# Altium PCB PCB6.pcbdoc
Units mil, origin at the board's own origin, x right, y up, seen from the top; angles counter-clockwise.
Board outline 1129.92 x 2677.83 mil, 2 copper layers (Top Layer, Bottom Layer); 45 components, 25 nets, 185 pads, 32 vias.
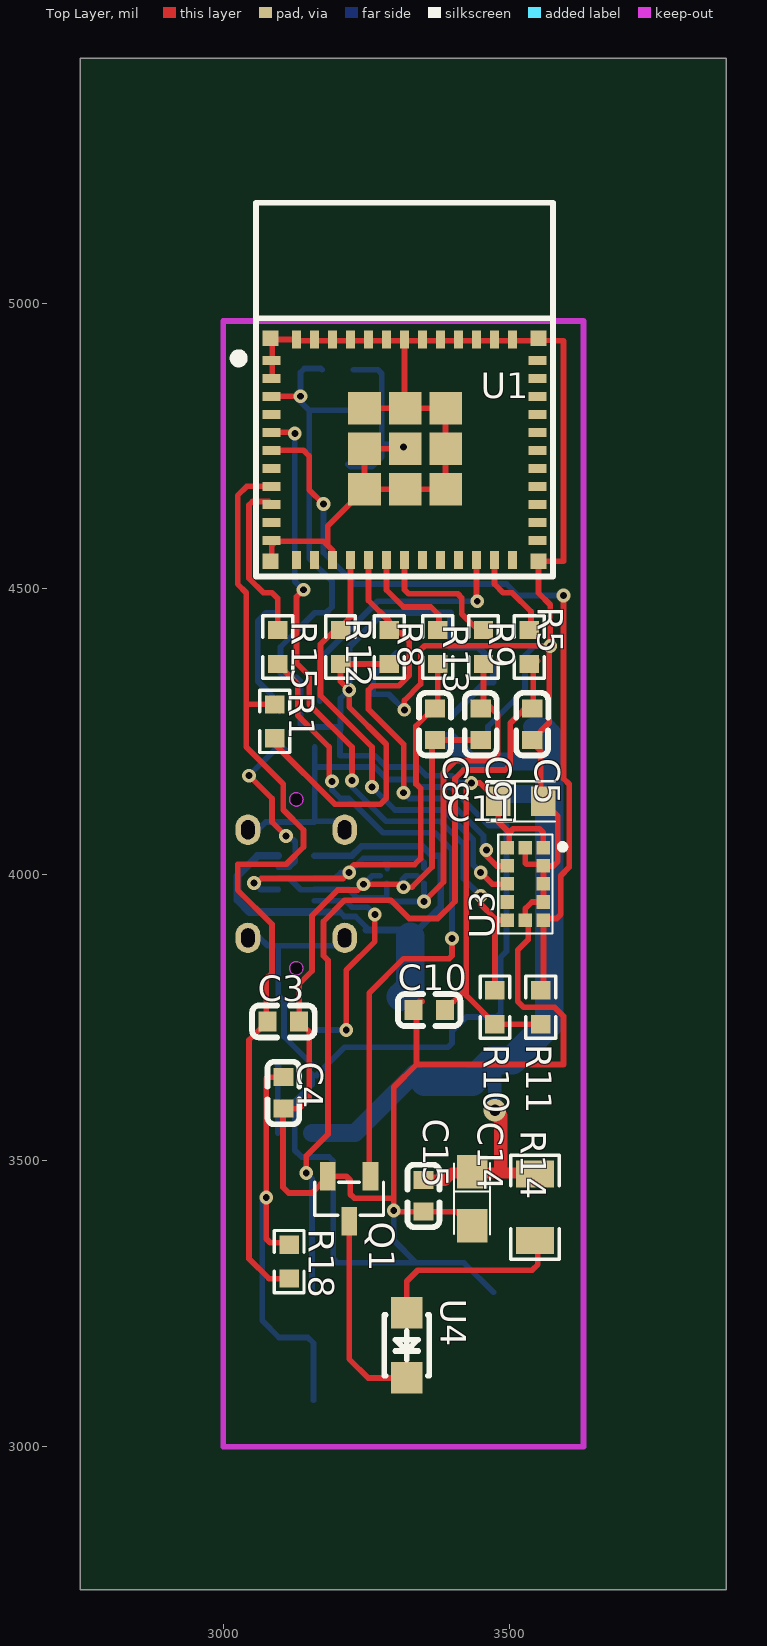
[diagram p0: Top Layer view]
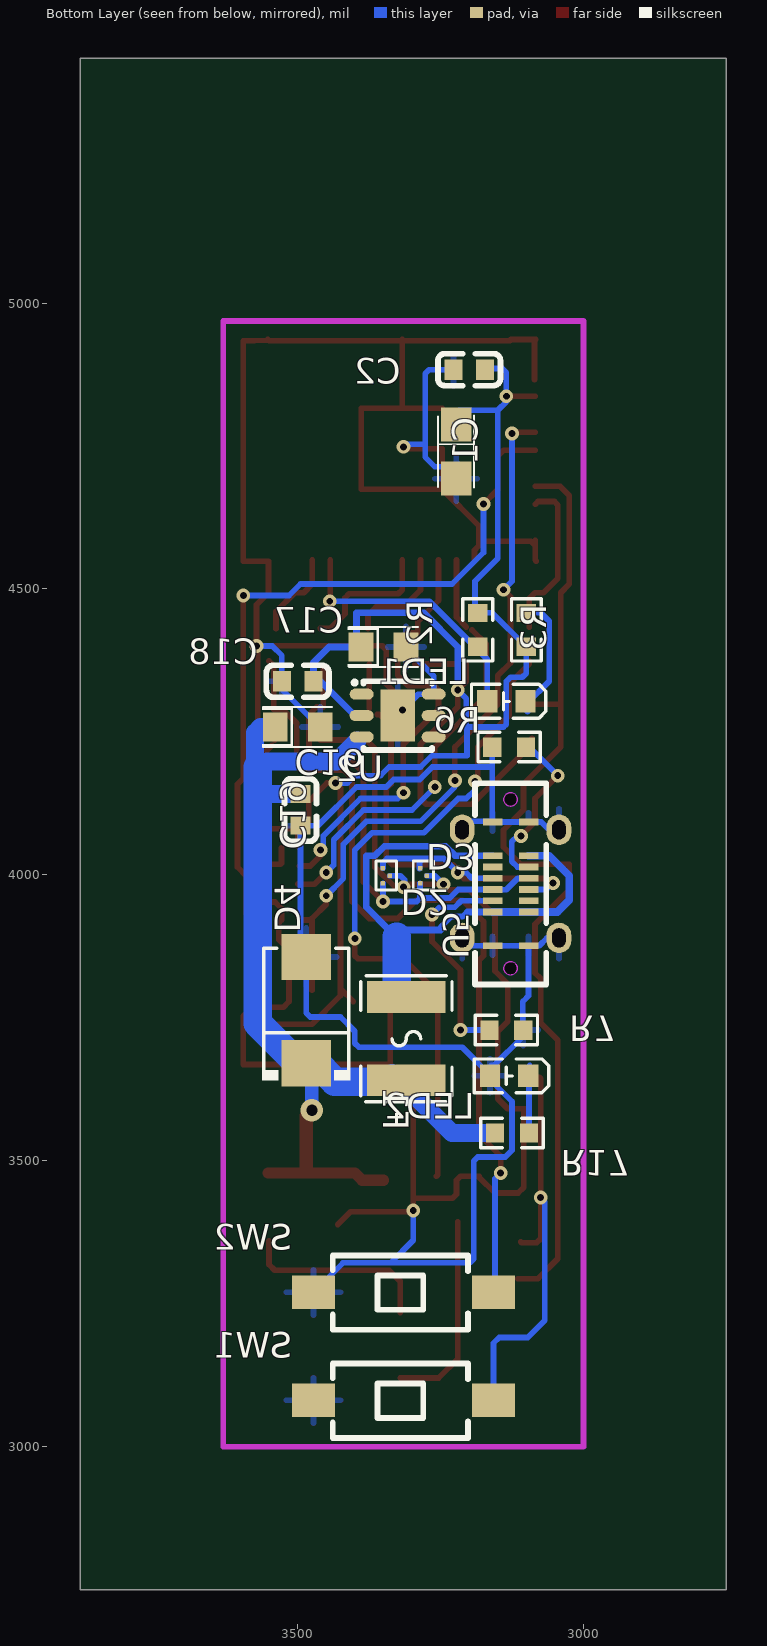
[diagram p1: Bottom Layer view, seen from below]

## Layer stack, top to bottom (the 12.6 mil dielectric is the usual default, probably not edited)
Top Layer: signal copper (thickness not stored)
Dielectric: dielectric 12.6, FR-4, Dk 4.8
Bottom Layer: signal copper (thickness not stored)

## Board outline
3879.92,2750 2750,2750 2750,5427.83 3879.92,5427.83

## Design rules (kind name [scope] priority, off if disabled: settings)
BoardOutlineClearance copperThickness1oz [All] p0: genericclearance=10 ignorepadtopadclearanceinfootprint=FALSE except(0: Arc-SplitContinuation Track-SplitContinuation SMDPad-SplitContinuation THPad-SplitContinuation Via-SplitContinuation Fill-SplitContinuation Poly-SplitContinuation Region-SplitContinuation Text-SplitContinuation; 6: Track-CutoutEdge SMDPad-CutoutEdge THPad-CutoutEdge Via-CutoutEdge Region-CutoutEdge; 11.8: Track-OutlineEdge SMDPad-OutlineEdge THPad-OutlineEdge Via-OutlineEdge Fill-OutlineEdge Region-OutlineEdge Poly-OutlineEdge Text-OutlineEdge Fill-CutoutEdge)
BoardOutlineClearance copperThickness2oz [All] p0: genericclearance=10 ignorepadtopadclearanceinfootprint=FALSE except(0: Arc-SplitContinuation Track-SplitContinuation SMDPad-SplitContinuation THPad-SplitContinuation Via-SplitContinuation Fill-SplitContinuation Poly-SplitContinuation Region-SplitContinuation Text-SplitContinuation; 6: Track-CutoutEdge SMDPad-CutoutEdge THPad-CutoutEdge Via-CutoutEdge Region-CutoutEdge; 11.8: Track-OutlineEdge SMDPad-OutlineEdge THPad-OutlineEdge Via-OutlineEdge Fill-OutlineEdge Region-OutlineEdge Poly-OutlineEdge Text-OutlineEdge Fill-CutoutEdge)
Clearance copperThickness1oz [(InNet('VDD33') OR InNet('GND') OR InNet('$3N5376') OR InNet('+5V_USB') OR InNet('GPIO12_USB_DN') OR InNet('GPIO13_USB_DP') OR InNet('$3N4848') OR InNet('$3N6215') OR InNet('$3N11377') OR InNet('$3N11381') OR InNet('$3N7934') OR InNet('$3N7054') OR InNet('$3N7060') OR InNet('GPIO2') OR InNet('GPIO3') OR InNet('I2C_SDA') OR InNet('I2C_SCL') OR InNet('$3N11357') OR InNet('GPIO4') OR InNet('$3N14553') OR InNet('$3N17638') OR InNet('$3N17354') OR InNet('$3N18951') OR InNet('$3N23650') OR InNet('$3N23645'))] p1: gap=7 ignorepadtopadclearanceinfootprint=FALSE except(4: Track-Track; 6: Track-SMDPad SMDPad-SMDPad Track-THPad SMDPad-THPad THPad-THPad Track-Via SMDPad-Via THPad-Via Via-Via SMDPad-Fill THPad-Fill Via-Fill Fill-Fill Track-Region SMDPad-Region THPad-Region Via-Region Region-Region Track-Poly SMDPad-Poly THPad-Poly Via-Poly Fill-Poly Region-Poly Poly-Poly Track-Text SMDPad-Text THPad-Text Via-Text Fill-Text Region-Text Poly-Text Text-Text; 6.9: Track-Hole SMDPad-Hole THPad-Hole Via-Hole Fill-Hole Region-Hole Poly-Hole Text-Hole Sheet-Hole; 11.8: Track-Fill Fill-Region Track-Sheet SMDPad-Sheet THPad-Sheet Via-Sheet Fill-Sheet Region-Sheet Poly-Sheet Text-Sheet)
Clearance copperThickness2oz [All] p1: gap=7 ignorepadtopadclearanceinfootprint=FALSE except(6: Track-SMDPad SMDPad-SMDPad Track-THPad SMDPad-THPad THPad-THPad Track-Via SMDPad-Via THPad-Via Via-Via SMDPad-Fill THPad-Fill Via-Fill Fill-Fill Track-Region SMDPad-Region THPad-Region Via-Region Region-Region Track-Poly SMDPad-Poly THPad-Poly Via-Poly Fill-Poly Region-Poly Poly-Poly Track-Text SMDPad-Text THPad-Text Via-Text Fill-Text Region-Text Poly-Text Text-Text; 6.9: Track-Hole SMDPad-Hole THPad-Hole Via-Hole Fill-Hole Region-Hole Poly-Hole Text-Hole Sheet-Hole; 8: Track-Track; 11.8: Track-Fill Fill-Region Track-Sheet SMDPad-Sheet THPad-Sheet Via-Sheet Fill-Sheet Region-Sheet Poly-Sheet Text-Sheet)
DiffPairsRouting differentialPair [All] p1: maxuncoupledlength=10 minlimit=6 maxlimit=6 mostfreqgap=6 toplayer_minwidth=5 toplayer_prefwidth=10 toplayer_maxwidth=100 bottomlayer_minwidth=5 bottomlayer_prefwidth=10 bottomlayer_maxwidth=100
PasteMaskExpansion pasteMaskExpansion [All] p1: expansion=0
PlaneConnect innerPlane [All] p1: planeconnectstyle=Relief reliefexpansion=20 reliefentries=4 reliefconductorwidth=10 reliefairgap=10
PolygonConnect copperRegion [All] p1: connectstyle=Relief reliefentries=4 reliefconductorwidth=10 polygonreliefangle="90 Angle" airgapwidth=10
RoutingVias viaSize [All] p1: viastyle="Through Hole" holewidth=12.0078 minholewidth=11.811 maxholewidth=248.0314 width=24.0158 minwidth=19.685 maxwidth=393.7008
SolderMaskExpansion solderMaskExpansion [All] p1: useseparateexpansions=TRUE expansion=2 expansionbottom=2
Width copperThickness1oz [All] p1: maxlimit=100 minlimit=5 preferedwidth=10
Width copperThickness2oz [All] p1: maxlimit=100 minlimit=8 preferedwidth=10

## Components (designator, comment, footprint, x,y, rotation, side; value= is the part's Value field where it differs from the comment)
C1 "" CASE-A_3216 3222.86,4740.18 r270 bottom
C2 "" C0603 3200,4883.5 r180 bottom
C3 "" C0603 3105,3743.5 r0 top
C4 "" C0603 3105,3618.5 r270 top
C5 "" C0603 3540,4263.5 r270 top
C8 "" C0603 3370,4263.5 r270 top
C9 "" C0603 3450,4263.5 r270 top
C10 "" C0603 3360,3763.5 r180 top
C11 "" CAP-SMD_L2.0-W1.3-FD 3520,4128.5 r0 top
C14 "" CASE-A_3216 3435,3433.5 r270 top
C15 "" C0603 3350,3438.5 r90 top
C16 "" C0603 3500,4338.5 r0 bottom
C17 "" CAP-SMD_L2.0-W1.3-FD 3350,4398.5 r180 bottom
C18 "" CAP-SMD_L2.0-W1.3-FD 3500,4258.5 r180 bottom
C19 "" C0603 3495,4113.5 r270 bottom
D2 "" X2SON-3_L1.0-W0.6-L 3280,3998.5 r0 bottom
D3 "" X2SON-3_L1.0-W0.6-L 3345,3998.5 r0 bottom
D4 "" SMB_L4.6-W3.6-LS5.3-RD 3485,3763.5 r90 bottom
F1 "" F1812 3310,3713.5 r90 bottom
LED1 "" LED0603-FD 3135,4303.5 r180 bottom
LED2 "" LED0603-FD 3130,3648.5 r180 bottom
Q1 "" SOT-23-3_L2.9-W1.3-P1.90-LS2.4-BR 3220,3433.5 r90 top
R1 "" R0603 3090,4268.5 r270 top
R2 "" R0603 3185,4428.5 r90 bottom
R3 "" R0603 3100,4428.5 r270 bottom
R5 "" R0603 3535,4398.5 r90 top
R6 "" R0603 3130,4223.5 r180 bottom
R7 "" R0603 3135,3728.5 r0 bottom
R8 "" R0603 3375,4398.5 r90 top
R9 "" R0603 3455,4398.5 r90 top
R10 "" R0603 3475,3768.5 r270 top
R11 "" R0603 3555,3768.5 r270 top
R12 "" R0603 3205,4398.5 r270 top
R13 "" R0603 3290,4398.5 r270 top
R14 "" R1206 3545,3418.5 r270 top
R15 "" R0603 3095,4398.5 r270 top
R17 "" R0603 3125,3548.5 r180 bottom
R18 "" R0603 3115,3323.5 r270 top
SW1 "" SW-SMD_L6.0-W3.3-LS8.0 3314.96,3080.96 r180 bottom locked
SW2 "" SW-SMD_L6.0-W3.3-LS8.0 3314.96,3269.88 r180 bottom locked
U1 "" WIFIM-SMD_61P-L16.6-W13.2-P0.80-ESP32-C6-MINI-1-N4 3316.83,4743.38 r0 top locked
U2 "" DFN-6_L3.0-W3.0-P0.95-BL-EP-1 3325,4278.5 r270 bottom
U3 "" OPTO-SMD_12P_VL53L3CXV0DH 3528.2,3984.01 r90 top locked
U4 "" LED-SMD_L3.0-W2.0-R-RD 3320.66,3177.16 r90 top locked
U5 "" TYPE-C-SMD_USB4120-03-C 3127.63,3984.25 r90 bottom locked

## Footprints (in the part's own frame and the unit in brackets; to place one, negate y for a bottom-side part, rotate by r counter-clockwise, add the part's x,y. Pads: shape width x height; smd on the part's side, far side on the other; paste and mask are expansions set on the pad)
C0603 [mm]
  rect 0.8x0.9 smd: 1(-0.7,0) 2(0.7,0)
  silkscreen extent -1.39,-0.71 1.39,0.71
CAP-SMD_L2.0-W1.3-FD [mm]
  rect 1.1x1.3 smd: 1(-1,0) 2(1,0)
  silkscreen extent -1.57,-0.89 1.52,0.89
CASE-A_3216 [mil]
  rect 59.05x53.5 smd: 1(-47.24,0) 2(47.24,0)
  silkscreen extent -63,-32 63,32
DFN-6_L3.0-W3.0-P0.95-BL-EP-1 [mm]
  oval 0.49x1.07 smd: 1(-0.95,-1.6) 2(0,-1.6) 3(0.95,-1.6) 4(0.95,1.6) 5(0,1.6) 6(-0.95,1.6)
  rect 2.3x1.55 smd: 7(0,0)
  silkscreen extent -1.56,-2 1.52,1.52
F1812 [mil]
  rect 55.38x137.76 smd: 1(-72.97,0) 2(72.97,0)
  silkscreen extent -110,-80 110,80
LED0603-FD [mm]
  rect 0.9x1 smd: 1(-0.85,0) 2(0.85,0)
  silkscreen extent -1.55,-0.75 1.75,0.75
LED-SMD_L3.0-W2.0-R-RD [mm]
  rect 1.4x1.4 smd: 1(1.45,0) 2(-1.45,0)
  silkscreen extent -1.35,-1 1.35,1
OPTO-SMD_12P_VL53L3CXV0DH [mm]
  rect 0.6x0.6 smd: 1(1.6,-0.8) 2(0.8,-0.8) 3(0,-0.8) 4(-0.8,-0.8) 5(-1.6,-0.8) 6(-1.6,0) 7(-1.6,0.8) 8(-0.8,0.8) 9(0,0.8) 10(0.8,0.8) 11(1.6,0.8) 12(1.6,0)
  silkscreen extent -2.2,-1.78 2.2,1.2
R0603 [mil]
  rect 31.75x34.02 smd: 1(-29.66,0) 2(29.66,0)
  silkscreen extent -55,-26 55,26
R1206 [mil]
  rect 47.54x66.97 smd: 1(-58.22,0) 2(58.22,0)
  silkscreen extent -91,-42 91,42
SMB_L4.6-W3.6-LS5.3-RD [mil]
  rect 80.61x86.31 smd: 1(-92.94,0) 2(92.94,0)
  silkscreen extent -123,-77 108,77
SOT-23-3_L2.9-W1.3-P1.90-LS2.4-BR [mm]
  rect 1.25x0.7 smd: 1(1,-0.95) 2(1,0.95) 3(-1,0)
  silkscreen extent -0.73,-1.53 0.73,1.53
SW-SMD_L6.0-W3.3-LS8.0 [mm]
  rect 1.9x1.5 smd: 1(-4,0) 2(4,0)
  silkscreen extent -3.14,-1.67 2.86,1.63
TYPE-C-SMD_USB4120-03-C [mm]
  oval 1.35x1.1 hole 0.6 slot 0.85 at 0 deg: 0(-2.4,-2.15) 0(-2.4,2.15) 0(2.4,-2.15) 0(2.4,2.15)
  rect 0.3x0.87 smd: A1(-2.75,0.8) A4(-1.25,0.8) A5(-0.75,0.8) A6(-0.25,0.8) A7(0.25,0.8) A8(0.75,0.8) A9(1.25,0.8) A12(2.75,0.8) B1(2.75,-0.8) B4(1.25,-0.8) B5(0.75,-0.8) B6(0.25,-0.8) B7(-0.25,-0.8) B8(-0.75,-0.8) B9(-1.25,-0.8) B12(-2.75,-0.8)
  Board Outline Layer circle w0.005: c-3.75,0 r0.3
  Board Outline Layer circle w0.005: c3.75,0 r0.3
  Board Outline Layer region: -3.75,0.3 -3.88,0.27 -3.985,0.187 -4.043,0.067 -4.043,-0.067 -3.985,-0.187 -3.88,-0.27 -3.75,-0.3 -3.75,-0.3 -3.62,-0.27 -3.516,-0.187 -3.458,-0.067 -3.458,0.067 -3.516,0.187 -3.62,0.27 -3.75,0.3
  Board Outline Layer region: 3.75,0.3 3.62,0.27 3.516,0.187 3.458,0.067 3.458,-0.067 3.516,-0.187 3.62,-0.27 3.75,-0.3 3.75,-0.3 3.88,-0.27 3.985,-0.187 4.043,-0.067 4.043,0.067 3.985,0.187 3.88,0.27 3.75,0.3
  Multi-Layer board cut-out: -3.75,0.3 -3.88,0.27 -3.985,0.187 -4.043,0.067 -4.043,-0.067 -3.985,-0.187 -3.88,-0.27 -3.75,-0.3 -3.75,-0.3 -3.62,-0.27 -3.516,-0.187 -3.458,-0.067 -3.458,0.067 -3.516,0.187 -3.62,0.27 -3.75,0.3
  Multi-Layer board cut-out: 3.75,0.3 3.62,0.27 3.516,0.187 3.458,0.067 3.458,-0.067 3.516,-0.187 3.62,-0.27 3.75,-0.3 3.75,-0.3 3.88,-0.27 3.985,-0.187 4.043,-0.067 4.043,0.067 3.985,0.187 3.88,0.27 3.75,0.3
  silkscreen extent -4.47,-1.58 4.47,1.58
WIFIM-SMD_61P-L16.6-W13.2-P0.80-ESP32-C6-MINI-1-N4 [mm]
  rect 0.8x0.4 smd: 1(-5.9,3.975) 2(-5.9,3.175) 3(-5.9,2.375) 4(-5.9,1.575) 5(-5.9,0.775) 6(-5.9,-0.025) 7(-5.9,-0.825) 8(-5.9,-1.625) 9(-5.9,-2.425) 10(-5.9,-3.225) 11(-5.9,-4.025) 25(5.9,-4.025) 26(5.9,-3.225) 27(5.9,-2.425) 28(5.9,-1.625) 29(5.9,-0.825) 30(5.9,-0.025) 31(5.9,0.775) 32(5.9,1.575) 33(5.9,2.375) 34(5.9,3.175) 35(5.9,3.975)
  rect 0.4x0.8 smd: 12(-4.8,-4.9) 13(-4,-4.9) 14(-3.2,-4.9) 15(-2.4,-4.9) 16(-1.6,-4.9) 17(-0.8,-4.9) 18(0,-4.9) 19(0.8,-4.9) 20(1.6,-4.9) 21(2.4,-4.9) 22(3.2,-4.9) 23(4,-4.9) 24(4.8,-4.9) 36(4.8,4.9) 37(4,4.9) 38(3.2,4.9) 39(2.4,4.9) 40(1.6,4.9) 41(0.8,4.9) 42(0,4.9) 43(-0.8,4.9) 44(-1.6,4.9) 45(-2.4,4.9) 46(-3.2,4.9) 47(-4,4.9) 48(-4.8,4.9)
  rect 1.45x1.45 smd: 49(-1.775,-1.75) 49(-1.775,0.05) 49(-1.775,1.85) 49(0.025,-1.75) 49(0.025,0.05) 49(0.025,1.85) 49(1.825,-1.75) 49(1.825,0.05) 49(1.825,1.85)
  rect 0.7x0.7 smd: 50(5.95,4.95) 51(5.95,-4.95) 52(-5.95,-4.95) 53(-5.95,4.95)
  silkscreen extent -7.57,-5.62 6.6,10.98
X2SON-3_L1.0-W0.6-L [mm]
  rect 0.2x0.2 smd: 1(-0.15,0) 2(0.15,-0.34) 3(0.15,0.34)
  silkscreen extent -0.45,-0.66 0.45,0.64

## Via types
v1: diameter 24.02, hole 12.01, Top Layer to Bottom Layer, 31 vias
v2: diameter 39.37, hole 19.68, Top Layer to Bottom Layer, 1 vias

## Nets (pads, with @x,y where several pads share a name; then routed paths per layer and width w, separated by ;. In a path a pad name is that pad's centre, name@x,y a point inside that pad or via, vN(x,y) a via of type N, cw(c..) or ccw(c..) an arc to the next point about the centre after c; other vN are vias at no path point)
$3N4848: LED1.1 R2.1 U1.22 | length 463.5
  Top Layer w10: U1.22 3442.81,4479.65 v1(3443.96,4478.5)
  Bottom Layer w10: LED1.1 3168.47,4376.97 3270,4478.5 v1(3443.96,4478.5)
$3N5376: C5.1 R5.1 SW2.2 | length 1476.6
  Top Layer w10: v1(3145,3478.5) 3145,3508.5 3182.93,3546.43 3182.93,3850.57 3175,3858.5 3175,3918.5 3211.95,3955.45 3293.01,3955.5 3325,3923.5 3375,3923.5 3405,3953.5 3405,4168.5 3420,4183.5 3492.57,4183.5 3501.72,4192.65 3501.72,4265.22 3525,4288.5 3541.91,4288.5 3541.91,4365.76 R5.1@3550,4373.84
  Bottom Layer w10: v1(3145,3478.5) 3155,3468.5 3155,3272.36 SW2.2
$3N6215: LED1.2 R3.1 | length 209.7
  Bottom Layer w10: R3.1@3089.66,4458.5 3075,4458.5 3060,4443.5 3060,4338.5 3098.1,4300.4 LED1.2@3098.1,4285.43
$3N7054: R8.2 U1.17 | length 186.3
  Top Layer w10: U1.17 3285.33,4498.17 3315,4468.5 3362.93,4468.5 3377.07,4454.36 R8.2@3377.07,4430.23
$3N7060: R9.2 U1.18 | length 240.3
  Top Layer w10: U1.18 3316.82,4498.5 3323.89,4491.43 3410,4491.43 3417.07,4484.36 3417.07,4456.43 3442.07,4431.43 3459.9,4431.43 R9.2@3460.67,4430.67
$3N7934: R5.2 U1.23 | length 155.8
  Top Layer w10: U1.23 3474.31,4508.5 3489.31,4493.5 3505,4493.5 3537.93,4460.57 R5.2@3537.93,4430.23
$3N11357: R14.2 U4.1 | length 338.2
  Top Layer w10: U4.1 3320.66,3289.17 3340,3308.5 3540,3308.5 3550,3318.5 R14.2@3550,3360.28
$3N11377: Q1.1 R15.2 | length 1196.7
  Top Layer w10: R15.2@3095,4373.84 R15.2 3130,4333.84 3130,4278.5 3185,4223.5 3185,4168.5 v1(3190,4163.5) ; Q1.1 3255,3475.27 3255,3793.5 3315,3853.5 3395,3853.5 3400,3858.5 v1(3400,3888.5)
  Bottom Layer w10: v1(3190,4163.5) 3190,4148.5 3205,4133.5 3219.14,4133.5 3279.14,4073.5 3370,4073.5 3400,4043.5 v1(3400,3888.5)
$3N11381: Q1.3 U4.2 | length 354.5
  Top Layer w10: Q1.3@3220,3393.5 3220,3153.5 3253.44,3120.07 U4.2
$3N14553: LED2.2 R17.2 | length 135.9
  Bottom Layer w10: LED2.2@3094.2,3666.56 LED2.2@3095.34,3665.42 ; R17.2 LED2.2@3095.34,3665.42 ; LED2.2 3096.53,3664.23 LED2.2@3095.34,3665.42
$3N17354: R7.2 U5.A5 | length 389
  Top Layer w10: v1(3215,3728.5) 3215,3833.5 3265,3883.5 v1(3265,3930.57)
  Bottom Layer w10: U5.A5 3213.78,3954.72 3225,3943.5 3252.07,3943.5 v1(3265,3930.57) ; R7.2 v1(3215,3728.5)
$3N17638: R6.2 U5.B5 | length 308.1
  Top Layer w10: v1(3045,4173.5) 3085,4133.5 3085,4092.42 v1(3109.55,4067.87)
  Bottom Layer w10: v1(3045,4173.5) 3095,4223.5 3103.53,4223.5 R6.2@3109.44,4217.6 ; U5.B5 3115.73,4013.78 3125.73,4023.78 3125.73,4057.78 3115.64,4067.87 v1(3109.55,4067.87)
$3N18951: F1.2 U5.A4 U5.A9 U5.B4 U5.B9 | length 961
  Bottom Layer w10: 3203.93,3935.04 3211.65,3927.32 3231.18,3927.32 3249.61,3908.9 3249.61,3903.5
  Bottom Layer w11.81: U5.A4 3203.46,3935.04 ; U5.A9 3224.96,4033.46 3241.55,4050.06 3348.45,4050.06 3365,4033.5 3380,4033.5 3380,3943.5 3340,3903.5 3249.61,3903.5
  Bottom Layer w13.78: U5.B4@3096.05,4033.46 3059.96,4033.46 3025,3998.5 3025,3955.92 3045.87,3935.04 U5.B9 U5.A4
  Bottom Layer w50: F1.2 3326.57,3803.04 3326.57,3891.93
$3N23645: C4.1 R18.1 SW1.2 | length 773.8
  Top Layer w10: C4.1 3077.56,3646.06 3075,3643.5 v1(3075,3435.76) 3075,3363.5 3082.07,3356.43 3108.27,3356.43 R18.1@3110,3358.16
  Bottom Layer w10: v1(3075,3435.76) 3067.93,3428.69 3067.93,3220.57 3097.48,3191.02 3147.48,3191.02 3157.48,3181.02 SW1.2
$3N23650: C3.1 R1.1 R18.2 U1.8 | length 1724.1
  Top Layer w10: U1.8 3040.9,4679.4 3025,4663.5 3025,4508.5 3040,4493.5 3040,4298.5 ; R1.1 3055.34,4298.16 3055,4298.5 3040,4298.5 ; R18.2 3079.66,3293.84 3045,3328.5 3045,3711.06 C3.1 3075,3745.94 3075,3818.5 3085,3828.5 3085,3913.5 3025,3973.5 3025,4018.5 3110,4018.5 3140,4048.5 3140,4078.5 3104.83,4113.68 3104.83,4158.68 3040,4223.5 3040,4298.5
+5V_USB: C14.1 C15.2 C18.1 C19.1 D4.1 F1.1 R14.1 R17.1 U2.3 | length 1636.9
  Top Layer w19.68: C15.2 3387.56,3466.06 3400,3478.5 R14.1@3551.78,3478.5
  Top Layer w23.62: v2(3475,3588.5) 3485,3578.5 3485,3488.5
  Bottom Layer w23.62: v2(3475,3588.5) D4.1@3475,3660.56
  Bottom Layer w31.5: R17.1 3230,3548.5 F1.1@3335,3653.5 ; U2.3@3395.38,4235 3431.87,4198.5 3553.3,4198.5 ; C19.1 3552.56,4141.06 3555,4143.5 ; C18.1 3565,4258.5 3575,4248.5 3575,4200.57
  Bottom Layer w50: F1.1@3352.03,3638.5 3435,3638.5 3472.06,3675.56 3505,3675.56 3570,3740.56 3570,4188.5
GND: C1.2 C2.1 C3.2 C4.2 C5.2 C8.2 C9.2 C10.2 C11.2 C14.2 C15.1 C16.2 C17.2 C18.2 C19.2 D2.1 D3.1 D4.2 LED2.1 Q1.2 R6.1 R7.1 SW1.1 SW2.1 U1.1 U1.2 U1.11 U1.14 U1.36 U1.37 U1.38 U1.39 U1.40 U1.41 U1.42 U1.43 U1.44 U1.45 U1.46 U1.47 U1.48 U1.49 U1.50 U1.51 U1.52 U1.53 U2.6 U2.7 U3.2 U3.3 U3.4 U3.6 U3.12 U5.0 U5.A1 U5.A12 U5.B1 U5.B12 | length 8924.5
  Top Layer w10: U1.52 3084.54,4550.47 3084.54,4576.29 ; U1.11 3084.54,4576.29 ; U1.2@3085.69,4866.26 3085.69,4897.76 3085.69,4934.17 3083.72,4936.14 3127.03,4936.14 3129,4934.17 3160.5,4934.17 3191.99,4934.17 U1.42@3316.83,4934.17 ; C4.2@3100,3590.94 C4.2 ; U1.14 3190.84,4567.66 3182.69,4575.81 ; U1.49@3246.94,4816.22 U1.49@3317.81,4816.22 ; v1(3316.59,4288.5) 3316.59,4305.09 3345,4333.5 3345,4393.5 3352.07,4400.57 3571.6,4400.57 v1(3571.83,4400.34) ; U1.42 U1.42@3316.83,4934.17 ; U1.49@3317.81,4745.35 3246.94,4745.35 U1.49@3246.94,4674.49 ; C10.2@3347.44,3778.5 3342.44,3778.5 3337.93,3773.99 3337.93,3668.5 ; C14.2@3430,3388.5 3407.56,3410.94 3365,3410.94 3299.81,3410.94 v1(3297.93,3412.83) 3297.93,3434.32 ; C9.2@3460,4235.94 3380,4235.94 3365,4220.94 3365,4013.5 3329.99,3978.5 v1(3315,3978.5) 3309.99,3983.5 v1(3245,3983.5) 3235,3973.51 3199.99,3973.5 3155,3928.5 3155,3831.75 3132.56,3809.31 C3.2 3150,3726.06 3150,3608.5 3132.44,3590.94 C4.2 ; U3.12 3528.19,4020.31 3530,4018.5 U3.2@3556.69,4018.5 ; C5.2 3570,4265.94 3570,4398.5 v1(3571.83,4400.34) ; C5.2@3545.4,4226.34 3555,4216.74 C11.2@3555,4128.5 ; C11.2 3585,4102.87 3585,4023.5 3576.99,4015.5 U3.2@3560,4015.5 ; U3.2 U3.2@3560,4015.5 ; 3084.54,4576.29 3091.76,4583.5 3175,4583.5 3182.69,4575.81 ; C4.2 3104.37,3590.31 3104.37,3453.5 3114.37,3443.5 3155,3443.5 3182.6,3471.1 Q1.2 3215,3472.87 3222.07,3465.8 3222.07,3441.39 3229.14,3434.32 3297.93,3434.32 ; 3182.69,4575.81 3182.69,4610.25 U1.49@3246.94,4674.49 ; U1.49@3246.94,4674.49 3317.81,4674.49 3388.67,4674.49 3388.67,4745.35 3388.67,4816.22 U1.49@3317.81,4816.22 ; 3297.93,3434.32 3297.93,3628.5 3337.93,3668.5 ; U1.42@3316.83,4934.17 3316.83,4817.2 U1.49@3317.81,4816.22 ; U1.42@3316.83,4934.17 3550.26,4934.17 3552.23,4936.14 3552.23,4934.94 3595,4933.5 3595,4548.5 U1.51 3551.08,4493.1 3571.83,4472.35 v1(3571.83,4400.34) ; 3337.93,3668.5 3595,3668.5 3595,3752.86 3579.36,3768.5 3525,3768.5 3515,3778.5 3515,3868.5 3533.19,3886.7 3533.19,3916.02 U3.6 3528.19,3940.97 3539.74,3952.51 3560,3952.51 U3.2@3560,4015.5
  Bottom Layer w10: U5.0@3042.98,3889.76 3063.74,3889.76 3077.52,3875.98 U5.B12 ; U5.0@3042.98,4078.74 3060.24,4078.74 3074.02,4092.52 U5.B1 U5.A12 U5.A12@3159.66,4093.06 ; LED2.1@3153.47,3652.5 3155,3650.96 3155,3633.5 3125,3603.5 3125,3518.5 3137.01,3506.5 3185,3506.5 3192.07,3499.43 3192.07,3328.5 3199.14,3321.43 3337.36,3321.43 ; R6.1 3159.66,4188.41 ; LED2.1@3161.13,3666.56 3156.94,3666.56 3106.13,3717.37 3106.13,3778.5 3096.13,3788.5 U5.B12 ; LED2.1 3163.47,3649.9 3212.07,3698.5 3392.93,3698.5 3400,3705.57 3400,3726.43 3425,3751.43 3477.93,3751.43 3485,3758.5 D4.2 3495,3866.44 C19.2 3464.8,4085.94 3397.24,4153.5 3345,4153.5 3331.94,4166.56 3286.52,4166.56 3264.67,4188.41 3159.66,4188.41 ; U5.0@3212.27,3889.76 3198.49,3875.98 U5.A1 U5.B12 ; U5.0@3212.27,4078.74 3197.51,4093.5 3160.1,4093.5 U5.A12@3159.66,4093.06 ; C1.2@3217.86,4717.94 3222.3,4713.5 3260,4713.5 3277.07,4730.57 3277.07,4753.11 ; C2.1 3270,4883.5 3277.07,4876.43 3277.07,4753.11 ; v1(3245,3983.5) 3259.99,3998.5 D2.1 ; v1(3297.93,3412.83) 3297.93,3360.86 3337.36,3321.43 ; C17.2@3302.76,4388.5 3262.01,4347.75 U2.6 3289.19,4315.9 v1(3316.59,4288.5) ; v1(3315,3978.5) 3312.93,3980.57 3312.93,3991.43 3320,3998.5 D3.1 ; v1(3315,4748.5) 3310.39,4753.11 3277.07,4753.11 ; C18.2@3462.76,4248.5 3462.76,4259.56 3527.56,4324.36 C16.2 3527.56,4383.5 3544.39,4400.34 v1(3571.83,4400.34) ; SW2.1 3420.89,3321.43 3337.36,3321.43 ; U5.A12@3159.66,4093.06 3159.66,4188.41
GPIO2: R10.1 U1.5 U3.7 | length 1248.3
  Top Layer w10: U1.5 3122.87,4773.89 v1(3125,4771.77) ; v1(3140,4498.5) 3127.93,4486.43 3127.93,4370.57 3150,4348.5 3150,4298.5 3225,4223.5 v1(3225,4165.04) ; v1(3450,3963.5) 3450,3948.5 3475,3923.5 ; R10.1 3475,3923.5 ; U3.7 3477.49,3921.02 3475,3923.5
  Bottom Layer w10: v1(3125,4771.77) 3125,4513.5 v1(3140,4498.5) ; v1(3225,4165.04) 3225,4153.5 3285,4093.5 3380,4093.5 3420,4053.5 3420,3993.5 v1(3450,3963.5)
GPIO3: R11.1 U1.6 U3.5 | length 1427.5
  Top Layer w10: U1.6 3140,4742.4 3150,4732.4 3150,4673.5 v1(3175,4648.5) ; R11.1 3560,3803.16 3560,3920.71 U3.5 3562.18,3923.5 3582.93,3923.5 3590,3930.57 3590,3998.5 3605,4013.5 3605,4158.5 3595,4168.5 v1(3595,4488.5)
  Bottom Layer w10: v1(3175,4648.5) 3175,4563.5 3230,4508.5 3495,4508.5 3515,4488.5 v1(3595,4488.5)
GPIO4: R15.1 U1.9 | length 287.4
  Top Layer w10: U1.9 3079.54,4652.91 3050.98,4652.91 3045,4646.93 3045,4518.5 3070,4493.5 3085,4493.5 3095,4483.5 R15.1@3095,4433.16
GPIO12_USB_DN: C8.1 D2.2 D3.2 R8.1 U5.A7 U5.B7 | length 944.4
  Top Layer w10: v1(3053.58,3985.89) 3058.58,3985.89 3066.2,3993.5 3209.41,3993.5 v1(3220,4004.09) 3220,4009.09 3228.75,4017.84 3334.52,4017.84 3345,4028.33 3345,4151.43 3337.93,4158.5 3336.89,4158.5 3336.89,4260.39 3357.08,4280.58 C8.1@3360.86,4280.58 ; C8.1@3375,4291.06 R8.1
  Bottom Layer w10: v1(3053.58,3985.89) 3065.06,3974.41 U5.B7 ; U5.A7 3195.59,3994.09 3205.59,4004.09 v1(3220,4004.09) 3244.41,4028.5 3280,4028.5 ; D2.2@3286.72,4011.08 3286.72,4021.08 3287.07,4021.43 3280,4028.5 ; D3.2 3350.9,4021.43 3343.83,4028.5 3280,4028.5
GPIO13_USB_DP: C9.1 D2.3 D3.3 R9.1 U5.A6 U5.B6 | length 848.2
  Top Layer w10: v1(3350.9,3953.5) 3385,3987.6 3385,4178.5 3406.09,4199.59 3468.76,4199.59 3480,4210.83 3480,4280.32 3466.82,4293.5 3455,4293.5 R9.1@3455,4365.69
  Bottom Layer w10: U5.B6 3115,3994.09 3135.29,3973.8 U5.A6@3158.51,3973.8 ; U5.A6 3219.09,3974.41 3234.1,3959.41 3285.9,3959.41 ; D2.3 3285.9,3959.41 ; D3.3 v1(3350.9,3953.5) 3291.81,3953.5 3285.9,3959.41
I2C_SCL: R13.1 U1.16 U3.10 | length 782.5
  Top Layer w10: U1.16 3253.83,4479.67 3290,4443.5 3290,4423.5 3310,4423.5 3325,4408.5 3325,4348.5 3307.07,4330.57 3260.9,4330.57 3253.83,4323.5 3253.83,4289.67 3315.28,4228.23 3315.28,4143.84 v1(3315,4143.57) ; v1(3460,4043.5) 3460,4033.5 3478.01,4015.5 U3.10
  Bottom Layer w10: v1(3315,4143.57) 3325.06,4133.5 3390,4133.5 3455,4068.5 3455,4048.5 v1(3460,4043.5)
I2C_SDA: R12.1 U1.15 U3.9 | length 782.5
  Top Layer w10: R12.1@3195,4428.16 3170,4403.16 3170,4313.5 3260,4223.5 v1(3260,4153.5) ; R12.1@3205,4433.5 3222.34,4450.84 U1.15 ; v1(3450,4004.01) 3470.51,3983.5 3498.81,3983.5 U3.9@3499.31,3984.01
  Bottom Layer w10: v1(3260,4153.5) 3300,4113.5 3385,4113.5 3437.01,4061.5 3437.01,4017 v1(3450,4004.01)
VDD33: C1.1 C2.2 C10.1 C11.1 C16.1 C17.1 R1.2 R2.2 R3.2 R10.2 R11.2 R12.2 R13.2 U1.3 U2.2 U3.1 U3.11 | length 3266.6
  Top Layer w10: U1.3 v1(3135,4836.88) ; R1.2 3090,4228.5 3195,4123.5 3275,4123.5 3285,4133.5 3285,4228.5 3220,4293.5 3220,4323.35 3205,4338.35 R12.2 ; R12.2@3220,4368.84 R13.2@3295,4368.84 ; C10.1@3402.56,3778.5 3425,3800.94 ; U3.11 3500,4050.3 3500,4073.5 ; R11.2 R10.2 3425,3788.84 3425,3800.94 ; U3.1 3559.69,4073.5 3552.62,4080.57 3507.07,4080.57 3500,4073.5 ; 3425,3800.94 3425,4151.81 v1(3433.7,4160.51) 3448.62,4160.51 C11.1 3480.63,4092.87 3500,4073.5
  Bottom Layer w10: C2.2 3170.37,4885.57 3142.07,4885.57 3135,4878.5 v1(3135,4836.88) 3135,4827.42 3150,4812.42 ; C1.1@3217.86,4812.42 3150,4812.42 ; v1(3220,4323.35) 3205,4308.35 3205,4258.5 ; v1(3433.7,4160.51) 3412.99,4160.51 3400,4173.5 3355,4173.5 3340,4188.5 3285,4188.5 3265,4208.5 3204,4208.5 3204,4253.5 3205,4254.51 3205,4258.5 ; 3150,4812.42 3150,4553.5 3190,4513.5 3190,4468.5 3180,4458.5 3160,4458.5 3100,4398.5 3100,4352.65 3107.07,4345.57 3127.93,4345.57 3135,4338.5 3135,4263.5 3139.92,4258.58 3205,4258.5
  Bottom Layer w11.81: v1(3220,4323.35) 3220,4398.5 3280,4458.5 3397.24,4458.5 3397.24,4398.5 3445,4398.5 3472.07,4371.43 3472.07,4337.25 3458.74,4337.25 3401.92,4280.42 U2.2@3399.92,4280.42
pads on no net: U1.4 U1.7 U1.10 U1.12 U1.13 U1.19 U1.20 U1.21 U1.24 U1.25 U1.26 U1.27 U1.28 U1.29 U1.30 U1.31 U1.32 U1.33 U1.34 U1.35 U2.1 U2.4 U2.5 U3.8 U5.A8 U5.B8

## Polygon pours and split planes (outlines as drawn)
GND on Bottom Layer (solid, remove dead copper, pour order 0): 3005,4963.5 3615,4963.5 3615,3008.5 3005,3008.5

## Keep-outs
Board Outline Layer:
  lines w10: 3000,3000 3629.92,3000 3629.92,4968.5 3000,4968.5 3000,3000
